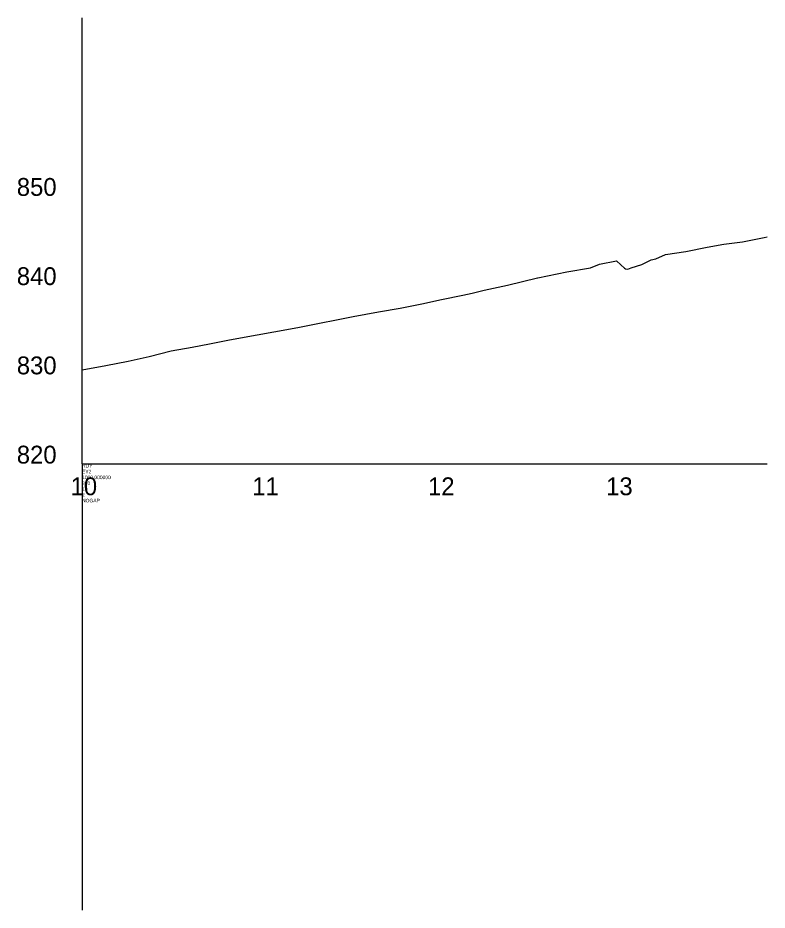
# Model space of a CAD drawing. Extents: x 570622 to 580296, y -55533 to -48575.
# Drawn here: x 577739 to 578159, y -53367 to -52867 of the extents above; entities that cross this region are included whole.
import ezdxf

# ---------------------------------------------------------------- set-up
doc = ezdxf.new("R2010")
doc.units = 0
for name, color, linetype in [('Exist Profile Cell', 7, 'Continuous'), ('Exist Vertical Profile Ground Line', 7, 'Continuous'), ('Exist Vertical Profile Horizontal Axis Label Major', 7, 'Continuous'), ('Exist Vertical Profile Vertical Axis Label', 7, 'Continuous')]:
    doc.layers.add(name, color=color, linetype=linetype)

msp = doc.modelspace()

# ---------------------------------------------------------------- linework, layer by layer
at = {"layer": 'Exist Profile Cell'}
for q in [(577775.33, -52866.61), (578159.42, -53116.61), (577775.33, -53366.61)]:
    msp.add_line((577775.33, -53116.61), q, dxfattribs=at)
at = {"layer": 'Exist Vertical Profile Ground Line'}
msp.add_lwpolyline([(577775.33, -53063.91), (577788.75, -53061.35), (577801.24, -53058.96), (577812.9, -53056.29), (577825.25, -53053.25), (577837.04, -53051.16), (577846.86, -53049.26), (577858.06, -53047.05), (577873.44, -53044.25), (577882.83, -53042.51), (577896.32, -53040.12), (577907.47, -53037.81), (577918.97, -53035.61), (577927.26, -53033.96), (577941.52, -53031.35), (577953.63, -53029.26), (577965.75, -53026.79), (577976.84, -53024.35), (577988.84, -53022.02), (577994.13, -53020.88), (578000.69, -53019.26), (578013.93, -53016.42), (578030.65, -53012.3), (578030.86, -53012.26), (578047.06, -53008.87), (578060.32, -53006.73), (578065.49, -53004.66), (578074.89, -53002.78), (578077.45, -53005.02), (578079.43, -53006.95), (578079.91, -53007.19), (578081.39, -53007.48), (578083.17, -53006.78), (578089.17, -53004.89), (578094.36, -53002.16), (578097, -53001.66), (578102.39, -52999.22), (578113.81, -52997.47), (578125.77, -52995.17), (578135.1, -52993.46), (578145.61, -52992.03), (578157.7, -52989.75), (578159.42, -52989.35)], dxfattribs=at)

# ---------------------------------------------------------------- texts
at = {"layer": 'Exist Profile Cell'}
for s, p in [('RDY', (577775.33, -53118.61)), ('EY2', (577775.33, -53121.86)), ('1000.000000', (577775.33, -53125.11)), ('820', (577775.33, -53128.36)), ('10', (577775.33, -53131.61)), ('2', (577775.33, -53134.86)), ('NOGAP', (577775.33, -53138.11))]:
    msp.add_text(s, height=2, dxfattribs=at).set_placement(p)
at = {"layer": 'Exist Vertical Profile Horizontal Axis Label Major'}
for s, p in [('10', (577768.91, -53134.11)), ('11', (577870.75, -53134.11)), ('12', (577969.3, -53134.11)), ('13', (578069.14, -53134.11))]:
    msp.add_text(s, height=10, dxfattribs=at).set_placement(p)
at = {"layer": 'Exist Vertical Profile Vertical Axis Label'}
for s, p in [('850', (577738.76, -52966.36)), ('840', (577738.76, -53016.36)), ('830', (577738.76, -53066.36)), ('820', (577738.76, -53116.36))]:
    msp.add_text(s, height=10, dxfattribs=at).set_placement(p)

doc.saveas('drawing.dxf')
